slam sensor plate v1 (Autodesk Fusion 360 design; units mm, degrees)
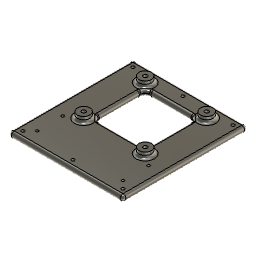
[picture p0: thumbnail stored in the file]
sketch "草图" plane through (0, 0, 0) normal (0, 0, 1) x axis (1, 0, 0)
  line L1 (-40, -43.5) -> (40, -43.5)
  line L2 (-40, 43.5) -> (-40, -43.5)
  line L3 (40, 43.5) -> (-40, 43.5)
  line L4 (40, -43.5) -> (40, 43.5)
  line L5 (-40, 43.5) -> (40, -43.5)
  line L6 (40, 43.5) -> (-40, -43.5)
  line L7 (-57.4549, 0) -> (-40, 0)
  line L8 (40, 0) -> (-57.4549, 0)
  line L9 (0, 1.6236) -> (0, 0)
  line L10 (0, 43.5) -> (0, 1.6236)
  line L11 (-21.5, -9.5) -> (21.5, -9.5)
  line L12 (-21.5, 33.5) -> (-21.5, -9.5)
  line L13 (21.5, 33.5) -> (-21.5, 33.5)
  line L14 (21.5, -9.5) -> (21.5, 33.5)
  line L15 (-21.5, 33.5) -> (21.5, -9.5)
  line L16 (21.5, 33.5) -> (-21.5, -9.5)
  line L17 (0, -24.5) -> (0, 0)
  line L18 (-30, -33.5) -> (30, -33.5)
  line L19 (-30, -15.5) -> (-30, -33.5)
  line L20 (30, -15.5) -> (-30, -15.5)
  line L21 (30, -33.5) -> (30, -15.5)
  line L22 (-30, -15.5) -> (30, -33.5)
  line L23 (30, -15.5) -> (-30, -33.5)
  line L24 (-18, 30) -> (-18, -6)
  line L25 (18, 30) -> (-18, 30)
  line L26 (18, -6) -> (18, 30)
  line L27 (-18, -6) -> (18, -6)
  circle C1 centre (0, 38.5) radius 1.125
  circle C2 centre (-35, 38.5) radius 1.125
  circle C3 centre (35, 38.5) radius 1.125
  circle C4 centre (0, -38.5) radius 1.125
  circle C5 centre (35, -38.5) radius 1.125
  circle C6 centre (-35, -38.5) radius 1.125
  circle C7 centre (-21.5, 33.5) radius 1.375
  circle C8 centre (21.5, 33.5) radius 1.375
  circle C9 centre (21.5, -9.5) radius 1.375
  circle C10 centre (-21.5, -9.5) radius 1.375
  circle C11 centre (-21.5, 33.5) radius 2.375
  circle C12 centre (21.5, 33.5) radius 2.375
  circle C13 centre (-21.5, -9.5) radius 2.375
  circle C14 centre (21.5, -9.5) radius 2.375
  circle C15 centre (-21.5, 33.5) radius 4.375
  circle C16 centre (21.5, 33.5) radius 4.375
  circle C17 centre (-21.5, -9.5) radius 4.375
  circle C18 centre (21.5, -9.5) radius 4.375
  circle C19 centre (-30, -15.5) radius 0.975
  circle C20 centre (30, -15.5) radius 0.975
  circle C21 centre (30, -33.5) radius 0.975
  circle C22 centre (-30, -33.5) radius 0.975
  point P6 (0, 0)
  point P1 (0, 0)
  point P7 (-40, 0)
  point P9 (40, 0)
  point P10 (0, 0)
  point P12 (0, 43.5)
  point P13 (0, 38.5)
  point P23 (0, 12)
  point P21 (-21.5, 33.5)
  point P24 (-21.5, 33.5)
  point P22 (21.5, 33.5)
  point P25 (21.5, 33.5)
  point P19 (21.5, -9.5)
  point P26 (21.5, -9.5)
  point P20 (-21.5, -9.5)
  point P27 (-21.5, -9.5)
  point P36 (0, 0)
  point P42 (0, -24.5)
  point P37 (0, -24.5)
  point P40 (-30, -15.5)
  point P43 (-30, -15.5)
  point P41 (30, -15.5)
  point P44 (30, -15.5)
  point P38 (30, -33.5)
  point P45 (30, -33.5)
  point P39 (-30, -33.5)
  point P46 (-30, -33.5)
  point P15 (35, 38.5)
  point P18 (35, -38.5)
  horizontal L1
  perpendicular L1 L2
  parallel L1 L3
  parallel L2 L4
  coincident L5 P6
  coincident L6 P6
  coincident P1 P6
  midpoint L2 P7
  perpendicular L2 L7
  midpoint L4 P9
  perpendicular L4 L8
  coincident P1 P10
  vertical L9
  midpoint L3 P12
  coincident L10 P13
  symmetric L8 C1 C4
  symmetric L8 C2 C6
  symmetric L8 C3 C5
  horizontal L11
  perpendicular L11 L12
  parallel L11 L13
  parallel L12 L14
  coincident L15 P23
  coincident L16 P23
  coincident L10 P23
  equal L11 L14
  coincident P21 P24
  coincident P22 P25
  coincident P19 P26
  coincident P20 P27
  equal C7 C8
  equal C7 C10
  equal C9 C10
  coincident P6 P36
  perpendicular L8 L17
  horizontal L18
  perpendicular L18 L19
  parallel L18 L20
  parallel L19 L21
  coincident L22 P42
  coincident L23 P42
  coincident P37 P42
  coincident P40 P43
  coincident P41 P44
  coincident P38 P45
  coincident P39 P46
  equal C19 C20
  equal C19 C22
  equal C21 C22
  dimension "d1" diameter C1 = 2.25
  dimension "d6" distance L4 P15 = 5
  dimension "d7" distance L3 P15 = 5
  dimension "d8" distance P15 P18 = 77
  dimension "d9" distance P19 P22 = 43
  dimension "d10" diameter C8 = 2.75
  dimension "d11" distance L3 L13 = 10
  dimension "d12" = 1
  dimension "d13" = 1
  dimension "d14" = 1
  dimension "d15" = 1
  dimension "d16" = 3
  dimension "d17" = 3
  dimension "d18" = 3
  dimension "d19" = 3
  dimension "d20" diameter C20 = 1.95
  dimension "d21" distance P38 P39 = 60
  dimension "d22" distance P38 P41 = 18
  dimension "d23" distance L1 L18 = 10
  dimension "d26" = 3.5
  dimension "d4" R-Pattern1-uDistance = 35
  dimension "d5" R-Pattern1-vDistance = 0
extrude "拉伸1" new body sketch "草图" profile of L1 L2 L3 L4 C1 C2 C3 C4 C5 C6 C15 C16 C17 C18 C19 C20 C21 C22 L24 L26 L25 L27 along normal blind 4
extrude "拉伸2" add sketch "草图" profile of C11 C12 C13 C14 C15 C16 C17 C18 along normal blind 8
extrude "拉伸3" sketch "草图" profile of C7 C8 C9 C10 C11 C12 C13 C14 blind -2
fillet "圆角1" radius 4
fillet "圆角2" radius 2
fillet "圆角3" radius 2
fillet "圆角4" radius 2
fillet "圆角5" radius 2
